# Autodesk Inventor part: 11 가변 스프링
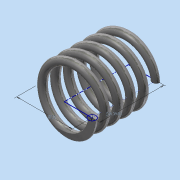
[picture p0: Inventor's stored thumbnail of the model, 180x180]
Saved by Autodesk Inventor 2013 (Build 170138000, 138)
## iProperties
Created: 2015-02
Part Number: 11 가변 스프링
Material: 강철, 탄소
Document SubType Name: Modeling
Designer: WINDOWS7
Density: 7.87 g/cm^3
Mass: 18.7439 g
Surface Area: 32.3998 cm^2
Volume: 2.3817 cm^3
Author: WINDOWS7
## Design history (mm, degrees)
sketch "스케치1"
  geometry: L1 (0, 0)-(11, 0); L2 (11, 0)-(11, 25.358); L3 (11, 25.358)-(0, 25.358); L4 (0, 25.358)-(0, 0); C1 r 1.5 at (11, 0)
  constraints: 8 end point, 2 parallel, 1 centre point, 1 coincident, 1 horizontal, 1 perpendicular
  dimensions: "d0" = 22 diameter of L2 L4; "d2" = 25.35829 distance of L1.end L2.end (derived); "d3" = 3 diameter of C1
feature "코일1" sketch "스케치1" pitch "d4" = 10; turns "d6" = 5; dims "d5" = 25.35829 (= d2), "d7" = 0, angle "d8" = 90 deg, angle "d9" = 90 deg, "d10" = 0, "d11" = 0
feature "분할1"
node "작업 평면1"
feature "분할2"
node "솔리드1"
other parameters: "d12" = 90 deg
